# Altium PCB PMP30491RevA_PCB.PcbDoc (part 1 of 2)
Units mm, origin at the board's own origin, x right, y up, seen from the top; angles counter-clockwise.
Board outline 40.64 x 55.88 mm, 4 copper layers (Top Layer, Layer 2, Layer 3, Bottom Layer), stack 2.028 mm thick; 56 components, 28 nets, 145 pads, 91 vias.
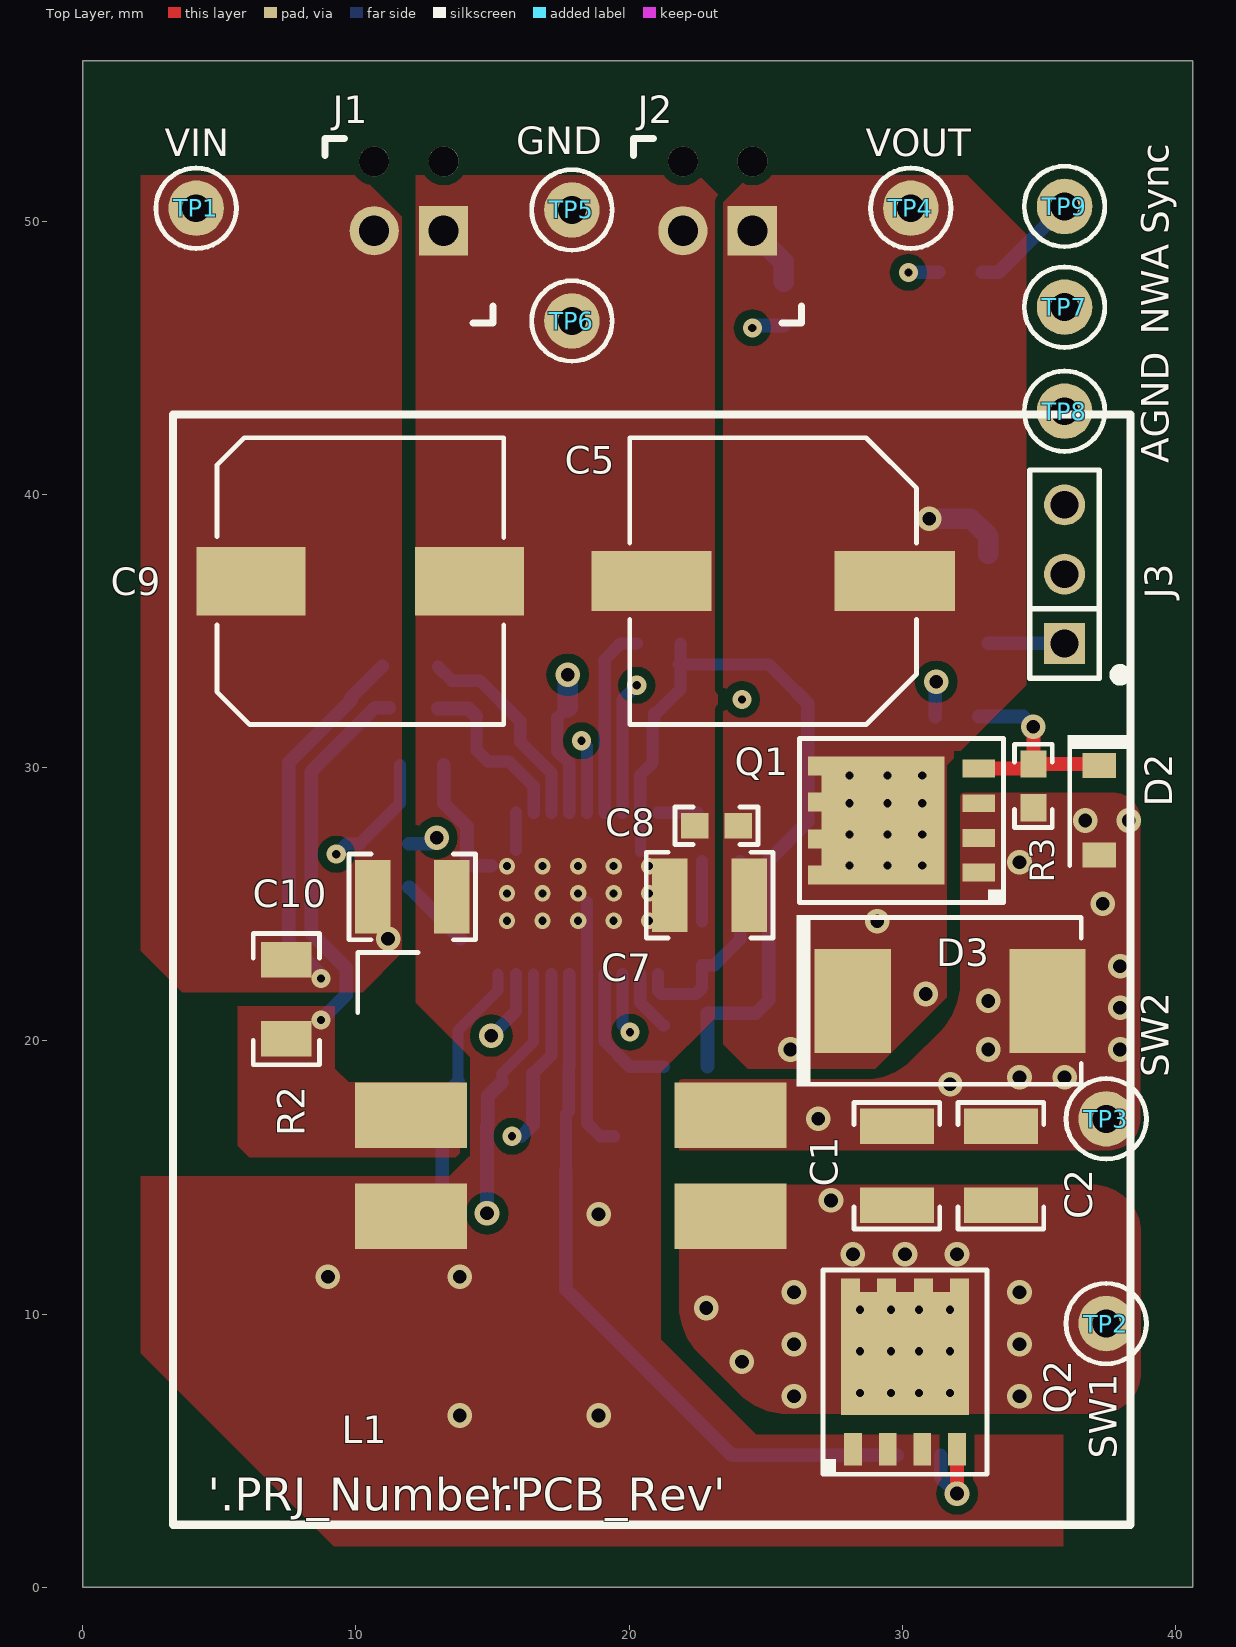
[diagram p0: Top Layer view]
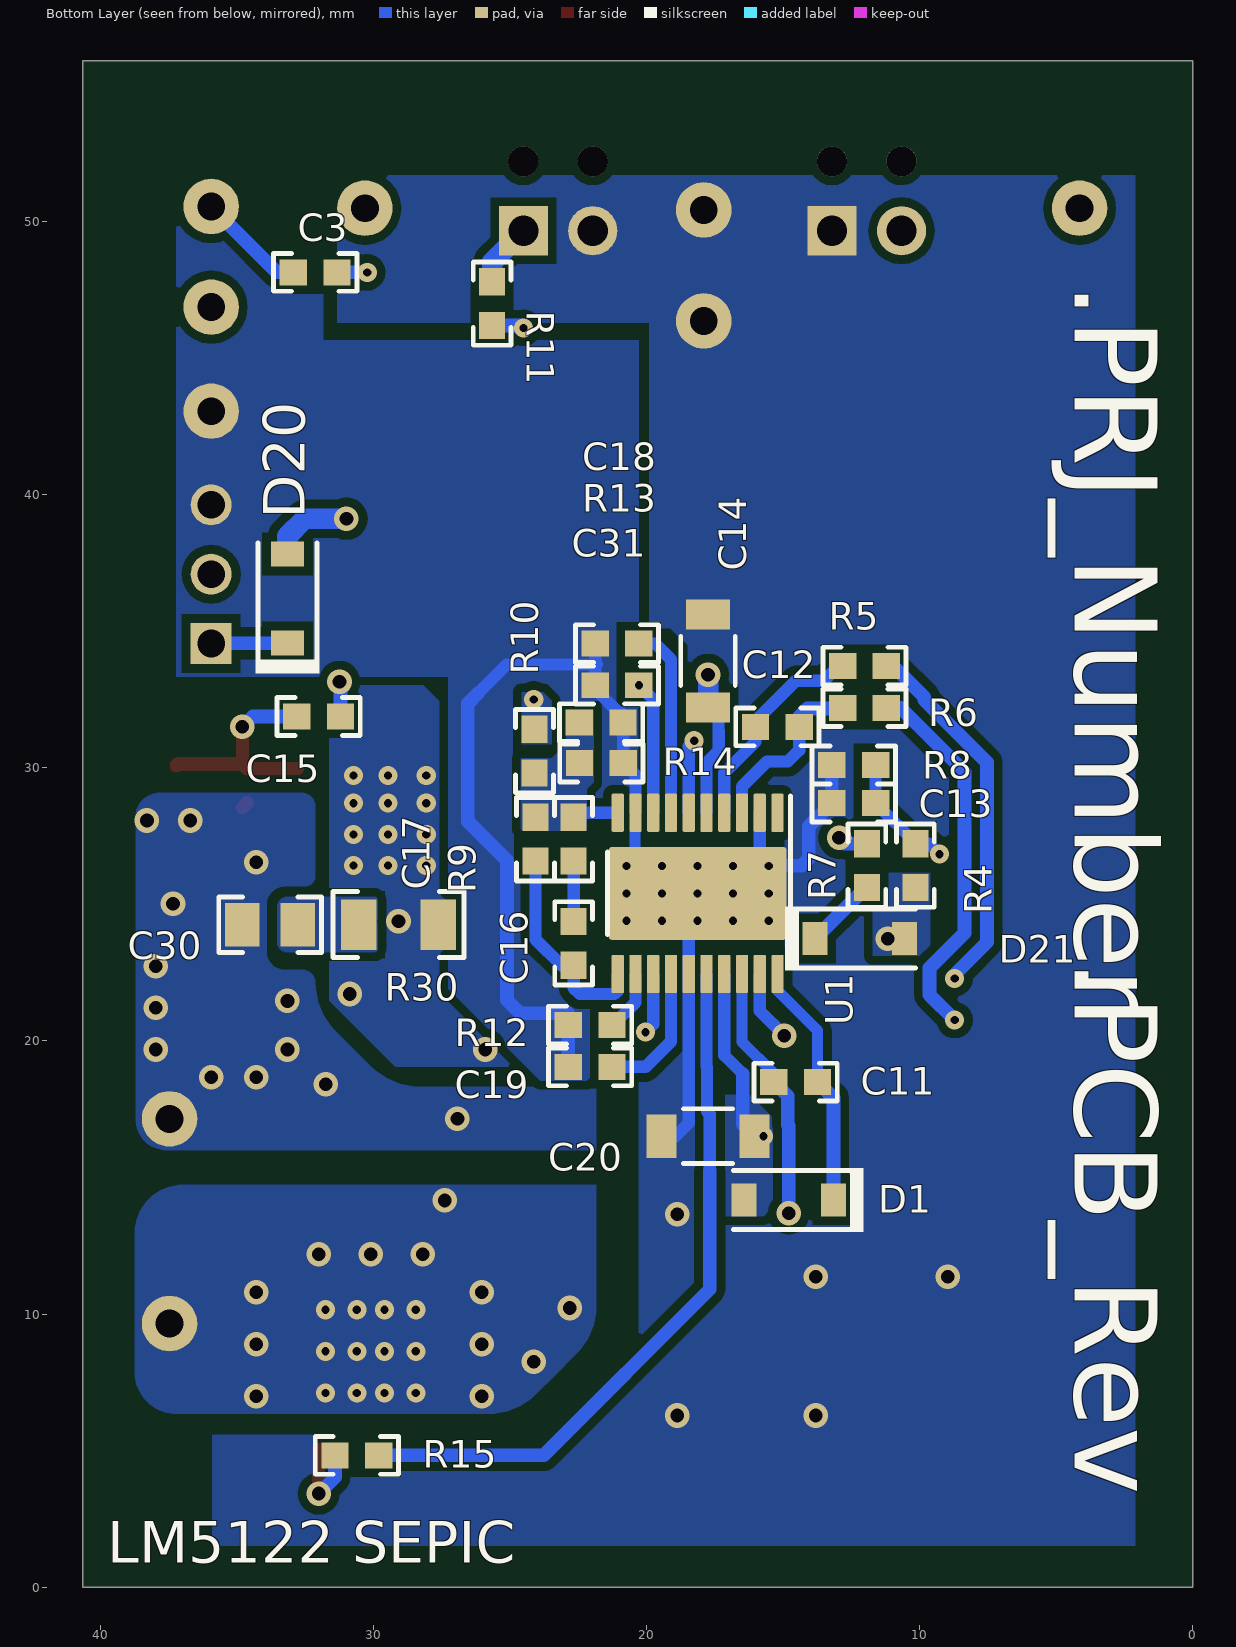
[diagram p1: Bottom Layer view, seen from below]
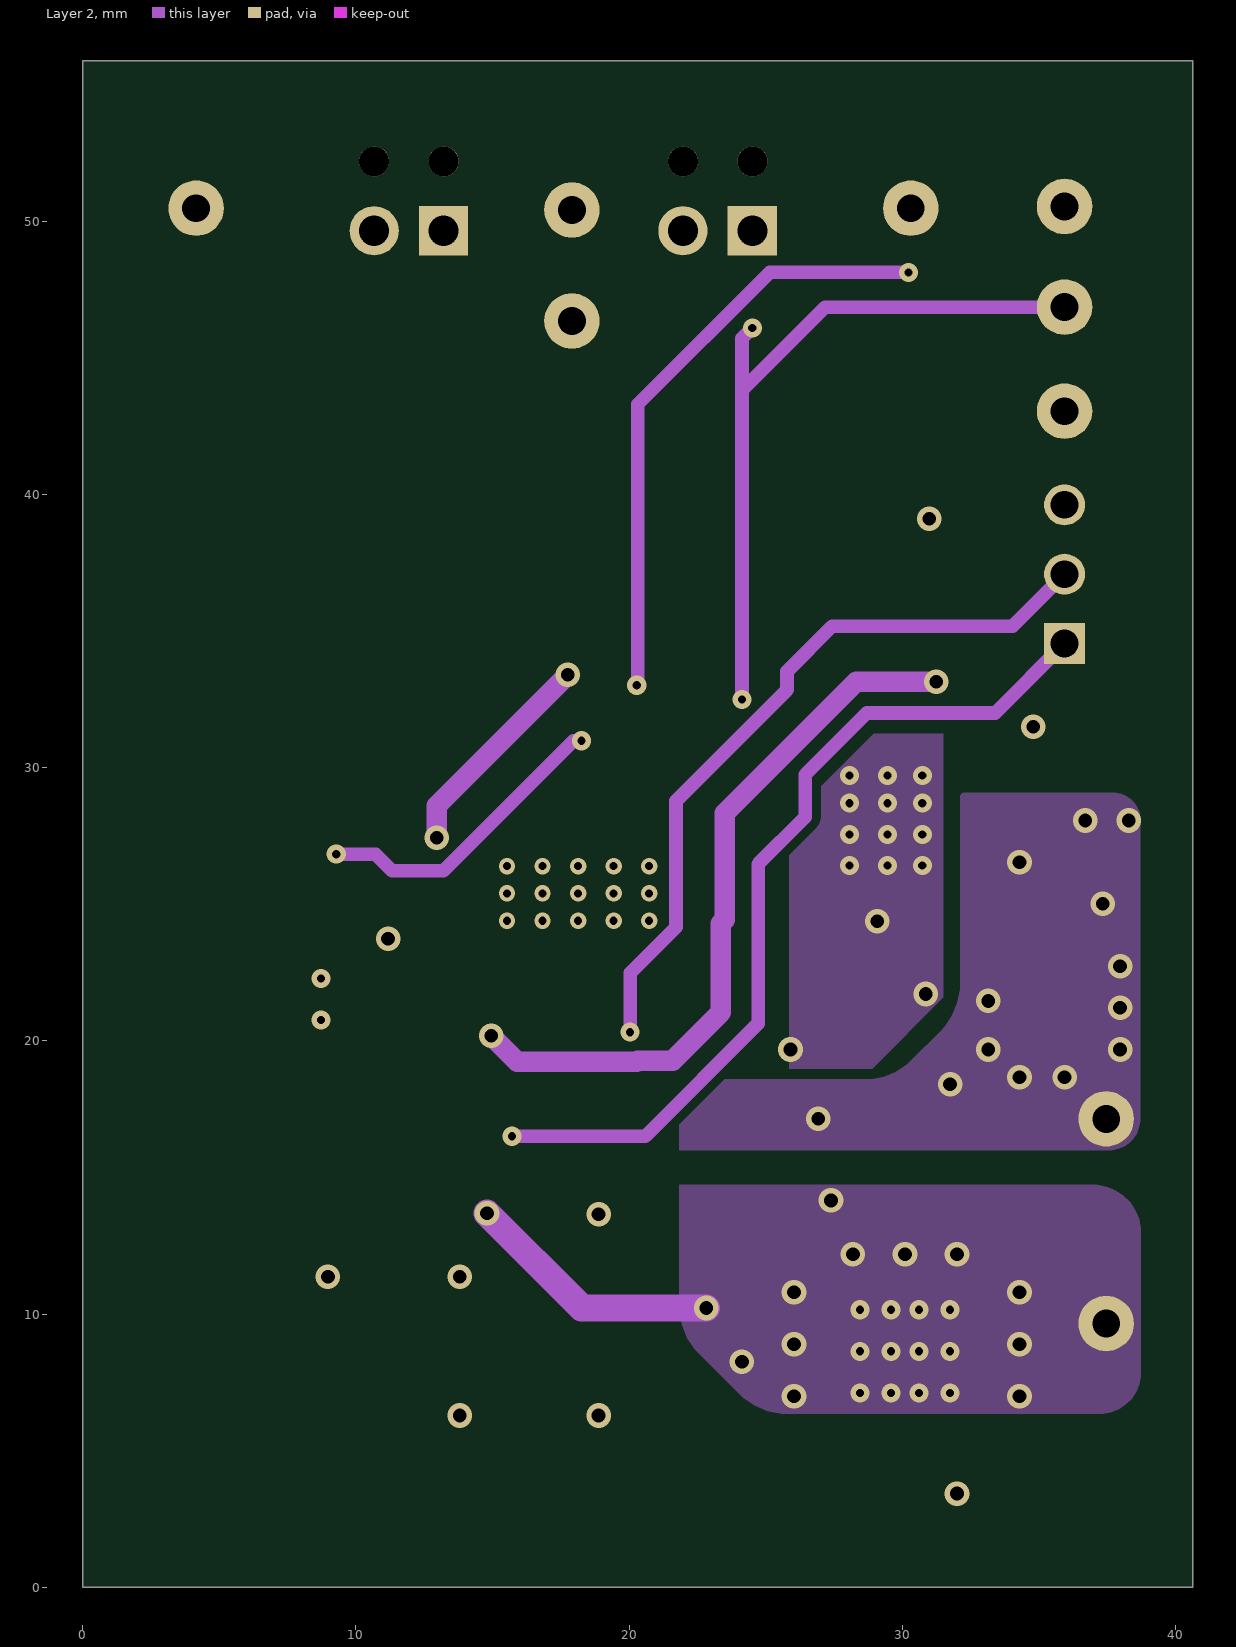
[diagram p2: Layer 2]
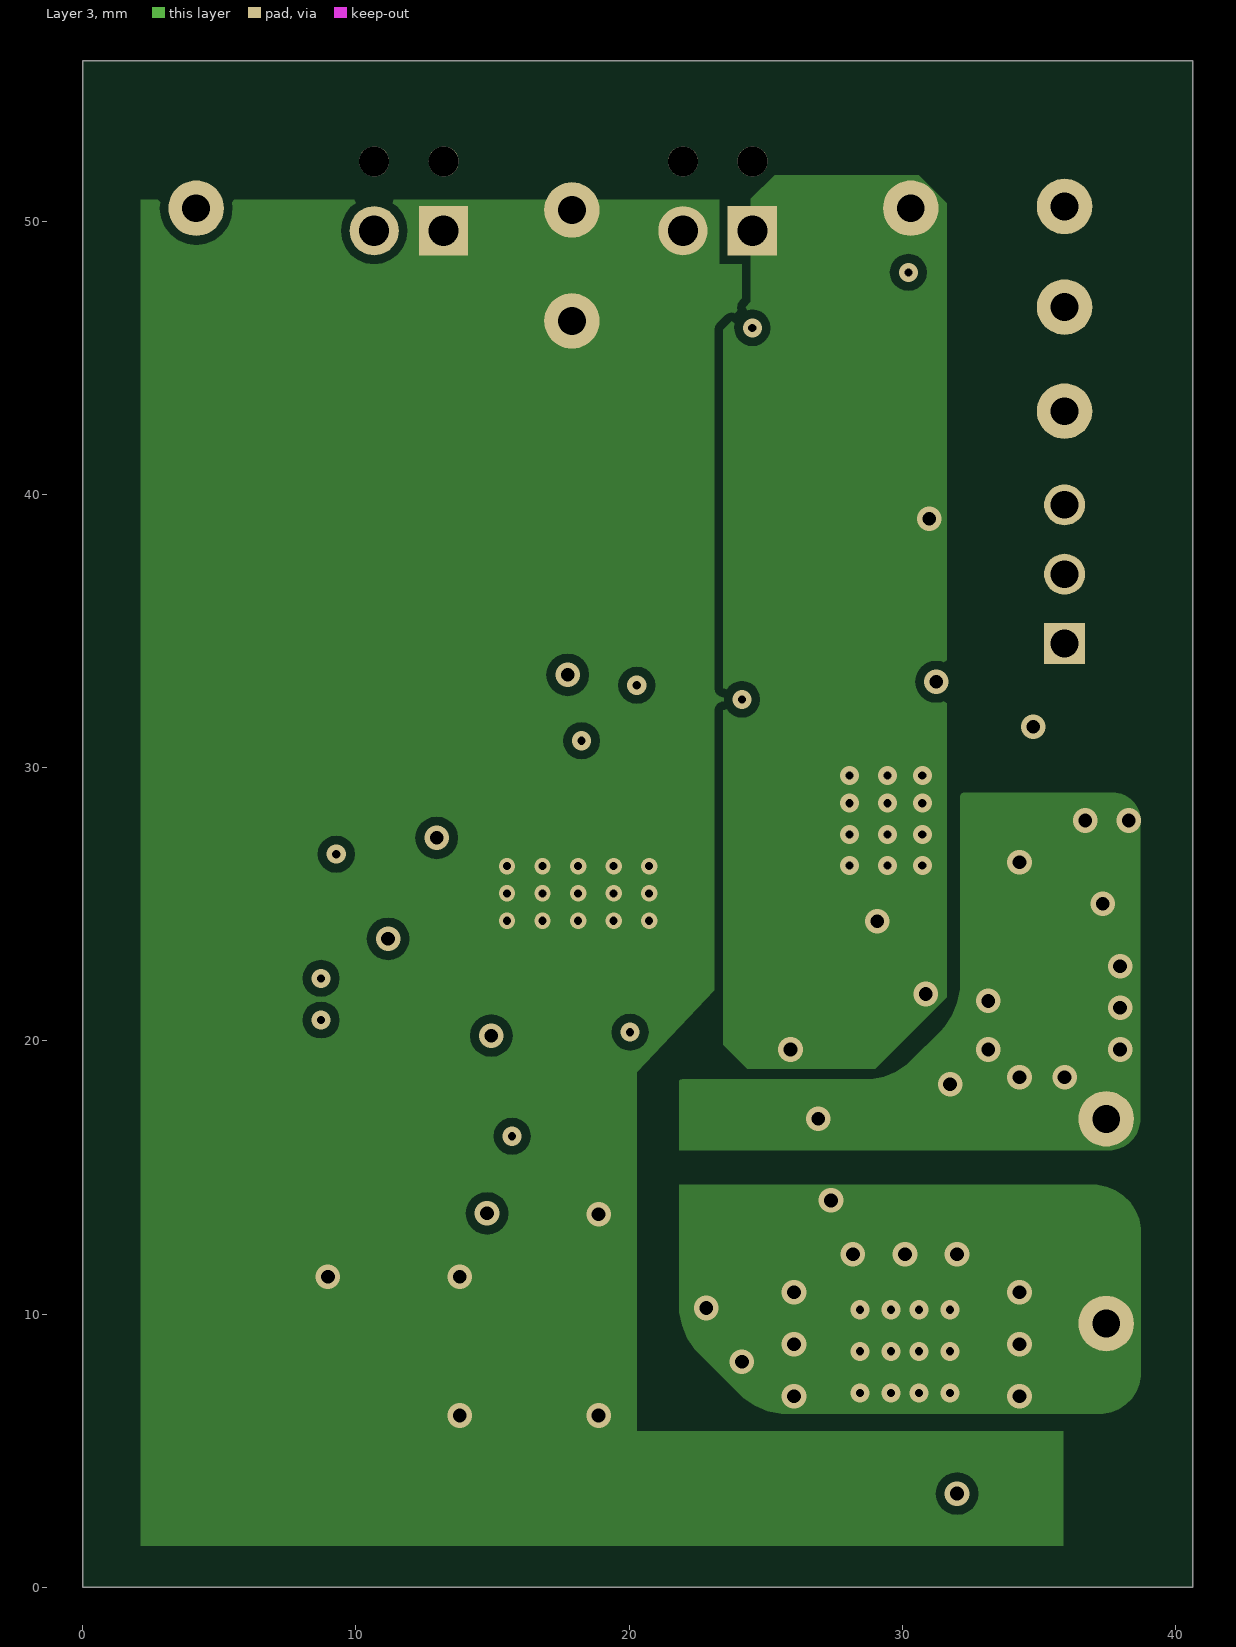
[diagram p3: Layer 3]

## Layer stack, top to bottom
Top Solder: solder mask 0.0102, Solder Resist, Dk 3.5
Top Layer: signal copper 0.0356
Dielectric1: core 1.5037, FR-4, Dk 4.8
Layer 2: signal copper 0.036
Dielectric 3: prepreg 0.127, Dk 4.2
Layer 3: signal copper 0.036
Dielectric 2: core 0.254, Dk 4.2
Bottom Layer: signal copper 0.0356
Bottom Solder: solder mask 0.0102, Solder Resist, Dk 3.5

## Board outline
0,0 40.64,0 40.64,55.88 0,55.88

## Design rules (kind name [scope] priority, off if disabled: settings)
AcuteAngle [All] p1: minimum=4.50000000000000E+0001 checktracksonly=FALSE
AssemblyTestPointUsage [All] p1: valid=2
BoardOutlineClearance BoardOutlineClearance_MountingHoles [OnCopper and InComponentClass('Mounting Holes')] p1: gap=1.016
BoardOutlineClearance BoardOutlineClearance_Poly [OnCopper and InPoly] p2: gap=0.5
BoardOutlineClearance [OnCopper and Not InComponentClass('Logo') and not InComponentClass('FiducialMark') and not InRegion(1000,500,4000,800)] p3: gap=1.5
Clearance Clearance_Keepouts [((IsTrack Or IsArc) And Not InPoly) And IsFree and IsKeepOut vs ((IsTrack Or IsArc) And Not InPoly) And IsFree and IsKeepOut] p1: gap=0
Clearance Clearance_U1_1 [TouchesRoom('Room_U1')] p2: gap=0.32 except(0.2: Arc-Track Arc-SMDPad Track-Track Track-SMDPad Track-Via SMDPad-SMDPad)
Clearance Clearance_U1 [InComponent('U1')] p3: gap=0.32 except(0.2: Arc-Track Arc-SMDPad Track-Track Track-SMDPad SMDPad-SMDPad)
Clearance Clearance_Poly [InPolygon] p4: gap=0.32
Clearance Clearance_Q [InComponent('Q1') or InComponent('Q2')] p5: gap=0.32 except(0.2: Arc-Track Arc-SMDPad Track-Track Track-SMDPad SMDPad-SMDPad; 0.3: Arc-Fill Track-Fill SMDPad-Fill)
Clearance [All] p6: gap=0.32
ComponentClearance ComponentClearance_MountingHoles_FiducialMarks [InComponentClass('Mounting Holes') vs InComponentClass('FiducialMark')] p1: gap=1.27 collisioncheckmode=3 verticalgap=0.254 showdistances=FALSE
ComponentClearance ComponentClearance_Shunt [InComponentClass('Header') vs InComponentClass('Shunt')] p2: gap=0 collisioncheckmode=3 verticalgap=0 showdistances=FALSE
ComponentClearance ComponentClearance_Logo [InComponentClass('Logo')] p3: gap=1.27 collisioncheckmode=3 verticalgap=0.254 showdistances=FALSE
ComponentClearance ComponentClearance_ScrewToNut [(HasFootprint('NY PMS 440 0025 PH')) vs (HasFootprint('Keystone_1902C'))] p4: gap=0.127 collisioncheckmode=3 verticalgap=0.254 showdistances=FALSE
ComponentClearance ComponentClearance_MountingHoles [InComponentClass('Mounting Holes')] p5: gap=6.35 collisioncheckmode=3 verticalgap=2540 showdistances=FALSE
ComponentClearance ComponentClearance_SmallPassives [HasFootprint('0201*') or HasFootprint('0402*') or HasFootprint('0508') or HasFootprint('0603*') or HasFootprint('0612') or HasFootprint('0805*') or HasFootprint('0815*') or HasFootprint('0830*') or HasFootprint('1206*') or HasFootprint('1210*') or HasFootprint('1808*') or HasFootprint('1812*') or HasFootprint('1825*') or HasFootprint('2010*') or HasFootprint('2220*') or HasFootprint('2225*') or HasFootprint('2512*') or HasFootprint('2728*') or HasFootprint('3518*') or HasFootprint('SOD-123') vs HasFootprint('0201*') or HasFootprint('0402*') or HasFootprint('0508') or HasFootprint('0603*') or HasFootprint('0612') or HasFootprint('0805*') or HasFootprint('0815*') or HasFootprint('0830*') or HasFootprint('1206*') or HasFootprint('1210*') or HasFootprint('1808*') or HasFootprint('1812*') or HasFootprint('1825*') or HasFootprint('2010*') or HasFootprint('2220*') or HasFootprint('2225*') or HasFootprint('2512*') or HasFootprint('2728*') or HasFootprint('3518*') or HasFootprint('SOD-123')] p6: gap=0.38 collisioncheckmode=3 verticalgap=0.254 showdistances=FALSE
ComponentClearance ComponentClearance_THtoSMT [IsThruComponent vs IsSMTComponent] p7: gap=1.016 collisioncheckmode=3 verticalgap=0.762 showdistances=FALSE
ComponentClearance ComponentClearance_THtoTH [IsThruComponent vs IsThruComponent] p8: gap=0.7 collisioncheckmode=3 verticalgap=0.762 showdistances=FALSE
ComponentClearance [All] p9: gap=0.762 collisioncheckmode=3 verticalgap=0.254 showdistances=FALSE
DiffPairsRouting [All] p1: maxlimit=2.54 minlimit=0.254 mostfreqgap=0.254 toplayer_minwidth=0.381 toplayer_maxwidth=0.381 toplayer_prefwidth=0.381 midlayer1_minwidth=0.381 midlayer1_maxwidth=0.381 midlayer1_prefwidth=0.381 midlayer2_minwidth=0.381 midlayer2_maxwidth=0.381 midlayer2_prefwidth=0.381 bottomlayer_minwidth=0.381 bottomlayer_maxwidth=0.381 bottomlayer_prefwidth=0.381 maxuncoupledlength=25.4
FabricationTestPointUsage TestPointUsage [All] p1: valid=2 allowmultiple=FALSE
FabricationTestpoint Testpoint [All] p1: side=3 testpointundercomponent=TRUE minsize=1.016 maxsize=2.54 preferedsize=1.524 minholesize=0 maxholesize=1.016 preferedholesize=0.813 testpointgrid=0.025 allowsidetop=TRUE allowsidebottom=TRUE usegrid=TRUE gridtolerance=0
FanoutControl Fanout_LCC [IsLCC] p1: bgadir=Out bgaviamode=Centered fanoutstyle=Auto fanoutdirection=Alternating viagrid=0.025 // Fanout_LCC (Default Rule)
FanoutControl Fanout_BGA [IsBGA] p2: bgadir=Out bgaviamode=Centered fanoutstyle=Auto fanoutdirection=Alternating viagrid=0.025 // Fanout_BGA (Default Rule)
FanoutControl Fanout_Default [All] p4: bgadir=Out bgaviamode=Centered fanoutstyle=Auto fanoutdirection=Alternating viagrid=0.025 // Fanout_Default (Default Rule)
FanoutControl Fanout_Small [(CompPinCount < 5)] p5: bgadir=Out bgaviamode=Centered fanoutstyle=Auto fanoutdirection=OutThenIn viagrid=0.025 // Fanout_Small (Default Rule)
HoleSize [All] p1: absolutevalues=TRUE maxlimit=6.375 minlimit=0.3 maxpercent=80.000 minpercent=20.000
MinimumAnnularRing MinimumAnnularRing_ThermalPadVias [IsVia and InAnyComponent] p1: minimumring=0.15
MinimumAnnularRing [All] p2: minimumring=0.2
MinimumSolderMaskSliver MinimumSolderMaskSliver_Logo [InComponentClass('Logo') vs InComponentClass('Logo')] p1: minsoldermaskwidth=0.018
MinimumSolderMaskSliver [All] p2: minsoldermaskwidth=0.1
PlaneConnect [All] p1: planeconnectstyle=Relief reliefexpansion=0.254 reliefentries=4 reliefconductorwidth=0.254 reliefairgap=0.254
PolygonConnect [All] p1: connectstyle=Direct reliefconductorwidth=0.254 reliefentries=4 polygonreliefangle="90 Angle" airgapwidth=0.254
RoomDefinition Room_U1 [InComponentClass('Components Class 1')] p1: confinementstyle=ConfineIn formatcopy=TRUE lockcomponents=FALSE outline 14.195,30.099 21.942,30.099 21.942,21.082 14.195,21.082
RoutingVias ThermalPadVias [IsVia and InAnyComponent] p1: holewidth=0.3 width=0.7 viastyle="Through Hole" minholewidth=0.3 minwidth=0.6 maxholewidth=0.5 maxwidth=1
RoutingVias [All] p2: holewidth=0.5 width=0.9 viastyle="Through Hole" minholewidth=0.3 minwidth=0.6 maxholewidth=1 maxwidth=1.8
SilkToBoardRegionClearance [Not ((IsComment or IsDesignator) And (Hide <> 'False')) and not InRegion(1000,500,4000,800)] p1:
SilkToSilkClearance SilkToSilkClearance_Pb-FreeLogo [(HasFootprint('Pb-Free_Overlay_Medium') OR HasFootprint('Pb-Free_Overlay_Small')) vs (HasFootprint('Pb-Free_Overlay_Medium') OR HasFootprint('Pb-Free_Overlay_Small'))] p1: silktosilkclearance=0
SilkToSilkClearance [All] p2: silktosilkclearance=0.102
SilkToSolderMaskClearance SilkToComponentPadClearance [IsPad and InAnycomponent] p1: minsilkscreentomaskgap=0.127 clearancetoexposedcopper=TRUE
SilkToSolderMaskClearance "Silk to Solder Mask Opening" [All] p2: minsilkscreentomaskgap=0.102 clearancetoexposedcopper=FALSE
SolderMaskExpansion [All] p1: expansion=0.05
Width [All] p1: maxlimit=2.54 minlimit=0.152 preferedwidth=0.254 checkconnectedcopper=TRUE
15 further rules are at their usual default settings.

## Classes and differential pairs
component class Header: J3

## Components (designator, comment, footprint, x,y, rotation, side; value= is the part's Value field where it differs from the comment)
C1 "GRM32ER71J106KA12L" 1210_270 29.804,15.43 r270 top
C2 "GRM32ER71J106KA12L" 1210_270 33.614,15.43 r270 top
C3 "GRM1885C1H101JA01D" 0603 32.131,48.133 r0 bottom
C5 "16SVPE470M" CAPSMT_62_JC0 25.273,36.83 r180 top
C7 "GRM32ER71E226KE15L" 1210_270 22.946,25.336 r180 top
C8 "GRM188R71E105KA12D" 0603 23.2,27.876 r180 top
C9 "EEHZC1J680P" SM_RADIAL_10BMM 10.16,36.83 r0 top
C10 "GRM32ER71J106KA12L" 1210_270 12.065,25.273 r0 top
C11 "GRM188R71E474KA12D" 0603 14.542,18.493 r0 bottom
C12 "GRM188R71H102KA01D" 0603 15.211,31.496 r0 bottom
C13 "GRM188R71H102KA01D" 0603 12.417,28.702 r0 bottom
C14 "GRM31CR72A225KA73L" 1206_190 17.751,33.909 r90 bottom
C15 "C1608X7R1C105K080AC" 0603 32.004,31.877 r180 bottom
C16 "GRM188R71E333KA01D" 0603 22.67,23.573 r90 bottom
C17 "GRM1885C1H101JA01D" 0603 24.067,27.383 r90 bottom
C18 "C1608X7R1H104K080AA" 0603 21.082,34.544 r0 bottom
C19 "GRM188R71E474KA12D" 0603 22.069,19.05 r180 bottom
C20 "GRM31CR71E106KA12L" 1206_180 17.751,16.51 r0 bottom
C30 "08051C471KAT2A" 0805_HV 33.782,24.257 r0 bottom
C31 "GRM1885C1H470JA01D" 0603 21.666,31.648 r180 bottom
D1 "MBR0580-TP" SOD-123 14.796,14.175 r0 bottom
D2 "MBR0580-TP" SOD-123 37.211,28.448 r270 top
D3 "B380-13-F" SMC 31.75,21.463 r0 top
D20 "MBR0580-TP" SOD-123 33.147,36.195 r90 bottom
D21 "MBR0580-TP" SOD-123 12.192,23.749 r180 bottom
J1 "1725656" CONN_1725656 11.938,49.657 r180 top
J2 "1725656" CONN_1725656 23.241,49.657 r180 top
J3 "PEC03SAAN" CONN_PEC03SAAN 35.941,37.084 r90 top
L1 "JA4590-AL" JA4590-AL 17.866,15.43 r0 top
Q1 "BSC117N08NS5ATMA1" PG-TDSON-8 29.972,28.067 r180 top
Q2 "BSC117N08NS5ATMA1" PG-TDSON-8 30.099,7.874 r90 top
R2 "WSLP1206R0150FEA" 1206 7.452,21.526 r270 top
R3 "CRCW06031K00FKEA" 0603 34.798,29.337 r90 top
R4 "CRCW0603100KFKEA" 0603 10.16,26.416 r270 bottom
R5 "ERJ-3GEY0R00V" 0603 12.024,33.718 r180 bottom
R6 "ERJ-3GEY0R00V" 0603 12.024,32.194 r180 bottom
R7 "CRCW06033R30JNEA" 0603 11.938,26.416 r90 bottom
R8 "CRCW060324K9FKEA" 0603 12.417,30.099 r180 bottom
R9 "CRCW060320K0FKEA" 0603 22.67,27.383 r270 bottom
R10 "CRCW060349K9FKEA" 0603 24.101,30.607 r90 bottom
R11 "CRCW060349R9FKEA" 0603 25.654,46.99 r90 bottom
R12 "CRCW060340K2FKEA" 0603 22.069,20.574 r180 bottom
R13 "CRCW060360K4FKEA" 0603 21.082,33.02 r180 bottom
R14 "CRCW06035K49FKEA" 0603 21.654,30.177 r0 bottom
R15 "CRCW06034R64FKEA" 0603 30.607,4.826 r0 bottom
R30 "PHP01206E10R0BST5" 1206 29.083,24.257 r180 bottom
TP1 "5000" Keystone5000 4.15,50.482 r0 top
TP2 "5002" Keystone5002 37.465,9.652 r90 top
TP3 "5002" Keystone5002 37.465,17.145 r90 top
TP4 "5000" Keystone5000 30.312,50.482 r0 top
TP5 "5001" Keystone5001 17.907,50.419 r0 top
TP6 "5001" Keystone5001 17.907,46.355 r0 top
TP7 "5003" Keystone5003 35.941,46.863 r180 top
TP8 "5001" Keystone5001 35.941,43.053 r90 top
TP9 "5002" Keystone5002 35.941,50.546 r0 top
U1 "LM5122MH/NOPB" PWP0020A_N 18.132,25.4 r270 bottom

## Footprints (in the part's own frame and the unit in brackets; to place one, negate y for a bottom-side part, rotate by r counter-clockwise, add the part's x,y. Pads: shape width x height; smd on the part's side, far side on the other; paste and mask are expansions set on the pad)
0603 [mm] "0603 from SM-752 data"
  rect 1x0.95 smd: 1(-0.8,0) 2(0.8,0)
  silkscreen extent -1.52,-0.69 1.52,0.69, body extent -0.87,-0.47 0.87,0.47, height 1
0805_HV [mil] "0805 with 30mil clearance between pads"
  rect 50x63 smd: 1(-40,0) 2(40,0)
  silkscreen extent -74,-40 74,40, body extent -43,-29 43,29, height 57
1206 [mm] "1206 from SM-752 data"
  rect 1.3x1.85 smd: 1(-1.45,0) 2(1.45,0)
  silkscreen extent -2.4,-1.21 2.4,1.21, body extent -1.7,-0.9 1.7,0.9, height 1.35
1206_180 [mm] "1206_180"
  rect 1.1x1.6 smd: 1(-1.7,0) 2(1.7,0)
  silkscreen extent -0.9,-1 0.9,1, body extent -1.75,-0.95 1.75,0.95, height 1.8
1206_190 [mm] "1206_190"
  rect 1.1x1.6 smd: 1(-1.7,0) 2(1.7,0)
  silkscreen extent -0.9,-1 0.9,1, body extent -1.75,-0.95 1.75,0.95, height 1.9
1210_270 [mm] "1210"
  rect 1.3x2.7 smd: 1(-1.45,0) 2(1.45,0)
  silkscreen extent -2.32,-1.57 2.32,1.57, body extent -1.7,-1.35 1.7,1.35, height 2.7
CAPSMT_62_JC0 [mm] "10 x 12.2mm:  Chemi-Con JC0"
  rect 4.4x2.2 smd: 1(-4.45,0) 2(4.45,0)
  silkscreen extent -5.25,-5.25 5.25,5.25, body extent -5.25,-5.25 5.25,5.25, height 12.7
CONN_1725656 [mm] "Phoenix Contact"
  rect 1.8x1.8 hole 1.1: 1(-1.27,0)
  round 1.8 hole 1.1: 2(1.27,0)
  round 1.1 hole 1.1 unplated: MH1(-1.275,-2.54) MH2(1.27,-2.54)
  silkscreen extent -3.08,-3.37 3.08,3.37, body extent -2.77,-3.1 2.77,3.1, height 8.52
CONN_PEC03SAAN [mm] "SULLINS"
  rect 1.5x1.5 hole 1.016: 1(-2.54,0)
  round 1.5 hole 1.016: 2(0,0) 3(2.54,0)
  silkscreen extent -3.89,-2.24 3.81,1.27, body extent -3.84,-1.3 3.84,1.3, height 8.38
JA4590-AL [mm] "COILCRAFT"
  rect 4.1x2.4 smd: 1(-5.85,1.85) 2(-5.85,-1.85) 3(5.85,-1.85) 4(5.85,1.85)
  silkscreen extent -7.8,5.6 -5.6,7.8, body extent -7.65,-7.65 7.65,7.65, height 14.25
Keystone5000 [mil] "For Keystone 500x miniature loop terminals"
  round 80 hole 40: 1(0,0)
  silkscreen extent -58,-58 58,58, body extent -49,-49 49,49, height 182
Keystone5001 [mil] "For Keystone 500x miniature loop terminals"
  round 80 hole 40: 1(0,0)
  silkscreen extent -58,-58 58,58, body extent -49,-49 49,49, height 182
Keystone5002 [mil] "For Keystone 500x miniature loop terminals"
  round 80 hole 40: 1(0,0)
  silkscreen extent -58,-58 58,58, body extent -49,-49 49,49, height 182
Keystone5003 [mil] "For Keystone 500x miniature loop terminals"
  round 80 hole 40: 1(0,0)
  silkscreen extent -58,-58 58,58, body extent -49,-49 49,49, height 182
PG-TDSON-8 [mm] "Infineon recommended land pattern"
  rect 1.2x0.65 smd: 1(-2.825,1.905) 2(-2.825,0.635) 3(-2.825,-0.635) 4(-2.825,-1.905)
  rect 0.5x0.7 smd: 5(3.175,-2) 6(3.175,-0.675) 7(3.175,0.675) 8(3.175,2)
  rect 4.5x4.7 smd paste-2.25: 9(0.675,0)
  silkscreen extent -3.74,-3 3.74,3, body extent -3.18,-2.89 3.18,2.9, height 1.1
PWP0020A_N [mm] "TSOP, 20-Leads, Body 6.5x4.4mm, Pitch 0.65mm, Exposed Pad, IPC Medium Density"
  rrect22% 1.4x0.45 smd: 1(-2.95,2.925) 2(-2.95,2.275) 3(-2.95,1.625) 4(-2.95,0.975) 5(-2.95,0.325) 6(-2.95,-0.325) 7(-2.95,-0.975) 8(-2.95,-1.625) 9(-2.95,-2.275) 10(-2.95,-2.925) 11(2.95,-2.925) 12(2.95,-2.275) 13(2.95,-1.625) 14(2.95,-0.975) 15(2.95,-0.325) 16(2.95,0.325) 17(2.95,0.975) 18(2.95,1.625) 19(2.95,2.275) 20(2.95,2.925)
  rrect6% 3.4x6.5 smd paste-2 mask-2: 21(0,0)
  rrect3% 3.15x4.35 on Bottom Paste: 21(0,0)
  rrect3% 3.15x4.35 on Bottom Solder: 21(0,0)
  silkscreen extent -3.55,-3.3 1.5,3.4, body extent -3.21,-3.25 3.21,3.25, height 1
SM_RADIAL_10BMM [mm] "Nichicon 10x10"
  rect 4x2.5 smd: 1(-4,0) 2(4,0)
  silkscreen extent -5.25,-5.25 5.25,5.25, body extent -5.25,-5.25 5.25,5.25, height 10.5
SMC [mil] "Molded Diode, 2-Leads, Body 6.9x5.8mm, IPC Medium Density, based on OnSemi component dimensions and land patterns"
  rect 110x150 smd: 1(-140.49,0) 2(140.49,0)
  silkscreen extent -221,-124 189,124, body extent -156,-116 156,116, height 91
SOD-123 [mm] "On Semi recommended land pattern"
  rect 0.915x1.22 smd: 1(-1.637,0) 2(1.637,0)
  silkscreen extent -2.74,-1.17 2.03,1.17, body extent -1.93,-0.9 1.93,0.9, height 1.35

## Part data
C1 C2 C10: "CAP, CERM, 10 µF, 63 V, +/- 10%, X7R, 1210"
C3 C17: "CAP, CERM, 100 pF, 50 V, +/- 5%, C0G/NP0, 0603"
C5: "CAP, Aluminum Polymer, 470 µF, 16 V, +/- 20%, 0.01 ohm, JC0 SMD"
C7: "CAP, CERM, 22 µF, 25 V, +/- 10%, X7R, 1210"
C8: "CAP, CERM, 1 µF, 25 V, +/- 10%, X7R, 0603"
C9: library part EEHZC1J560P, "CAP, Polymer Hybrid, 68 µF, 63 V, +/- 20%, 30 ohm, 10x10 SMD"
C11 C19: "CAP, CERM, 0.47uF, 25V, +/-10%, X7R, 0603"
C12 C13: "CAP, CERM, 1000pF, 50V, +/-10%, X7R, 0603"
C14: "CAP, CERM, 2.2 µF, 100 V, +/- 10%, X7R, 1206_190"
C15: "CAP, CERM, 1 µF, 16 V, +/- 10%, X7R, 0603"
C16: "CAP, CERM, 0.033 µF, 25 V, +/- 10%, X7R, 0603"
C18: "CAP, CERM, 0.1 µF, 50 V, +/- 10%, X7R, 0603"
C20: "CAP, CERM, 10 µF, 25 V, +/- 10%, X7R, 1206"
C30: "CAP, CERM, 470 pF, 100 V, +/- 10%, X7R, 0805"
C31: "CAP, CERM, 47 pF, 50 V, +/- 5%, C0G/NP0, 0603"
D1 D2 D20 D21: "Diode, Schottky, 80 V, 0.5 A, SOD-123"
D3: "Diode, Schottky, 80 V, 3 A, SMC"
J1 J2: "Terminal Block, 100mil, 2x1, 6A, 63V, TH"
J3: "Header, 100mil, 3x1, Tin, TH"
L1: "Coupled inductor, 22 µH, 7.8 A, 0.028 ohm, SMD"
Q1 Q2: "MOSFET, N-CH, 80 V, 49 A, PG-TDSON-8"
R2: "RES, 0.015, 1%, 1 W, 1206"
R3: "RES, 1.00k ohm, 1%, 0.1W, 0603"
R4: "RES, 100 k, 1%, 0.1 W, 0603"
R5 R6: "RES, 0 ohm, 5%, 0.1W, 0603"
R7: "RES, 3.3 ohm, 5%, 0.1W, 0603"
R8: "RES, 24.9 k, 1%, 0.1 W, 0603"
R9: "RES, 20.0 k, 1%, 0.1 W, 0603"
R10: "RES, 49.9k ohm, 1%, 0.1W, 0603"
R11: "RES, 49.9, 1%, 0.1 W, 0603"
R12: "RES, 40.2 k, 1%, 0.1 W, 0603"
R13: "RES, 60.4 k, 1%, 0.1 W, 0603"
R14: "RES, 5.49 k, 1%, 0.1 W, 0603"
R15: "RES, 4.64, 1%, 0.1 W, 0603"
R30: "RES, 10.0, 0.1%, 1 W, 1206"
TP1 TP4: "Test Point, Miniature, Red, TH"
TP2 TP3 TP9: "Test Point, Miniature, White, TH"
TP5 TP6 TP8: "Test Point, Miniature, Black, TH"
TP7: "Test Point, Miniature, Orange, TH"
U1: library part LM5122MHX/NOPB, "Wide Input Synchronous Boost Controller with Multiple Phase Capability, PWP0020A (TSSOP-20)"

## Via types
v1: diameter 0.9, hole 0.5, Top Layer to Bottom Layer, 21 vias
v2: diameter 0.7, hole 0.3, Top Layer to Bottom Layer, 19 vias
v3: diameter 0.9, hole 0.5, Top Layer to Bottom Layer, tented top, 19 vias
v4: diameter 0.7, hole 0.3, Top Layer to Bottom Layer, tented top, 9 vias
v5: diameter 0.6, hole 0.3, Top Layer to Bottom Layer, 6 vias
v6: diameter 0.6, hole 0.3, Top Layer to Bottom Layer, tented both sides, 6 vias
v7: diameter 0.7, hole 0.3, Top Layer to Bottom Layer, tented bottom, 5 vias
v8: diameter 0.6, hole 0.3, Top Layer to Bottom Layer, tented top, 3 vias
v9: diameter 0.9, hole 0.5, Top Layer to Bottom Layer, tented bottom, 2 vias
v10: diameter 0.7, hole 0.3, Top Layer to Bottom Layer, tented both sides, 1 vias

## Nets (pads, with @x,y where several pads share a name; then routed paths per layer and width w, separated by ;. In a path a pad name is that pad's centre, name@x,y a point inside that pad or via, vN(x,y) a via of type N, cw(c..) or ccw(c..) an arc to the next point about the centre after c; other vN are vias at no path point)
12V: C5.1 C7.1 C8.1 D3.1 D20.2 J2.1 Q1.5 Q1.6 Q1.7 Q1.8 Q1.9 R11.2 R30.2 TP4.1 | length 5.4
  Bottom Layer w0.75: J2.1@24.511,49.657 25.654,48.514 R11.2@25.654,47.79 ; v3(30.988,39.116) 32.512,39.116 33.147,38.481 D20.2@33.147,37.832
  other v2: 30.734,26.416 30.734,27.559 28.067,28.702 29.464,28.702 30.734,28.702 29.464,29.718 30.734,29.718
  other v3: 25.908,19.685 30.861,21.717 29.083,24.384
  other v4: 28.067,29.718
  other v7: 28.067,26.416 29.464,26.416 28.067,27.559 29.464,27.559
GND: C5.2 C7.2 C8.2 C9.2 C10.2 C13.2 C14.2 C18.2 C19.1 C20.2 C31.2 J1.1 J2.2 J3.3 L1.2 Q2.1 Q2.2 Q2.3 R8.1 R12.1 R13.1 R14.1 TP5.1 TP6.1 TP8.1 U1.2 U1.9 U1.15 U1.21@18.132,25.4 | length 44.9
  Bottom Layer w0.4: U1.9@20.407,28.35 U1.21@20.418,26.924
  Bottom Layer w0.45: v6(15.532,26.4) U1.21@15.532,26.461 ; U1.21@15.857,26.989 U1.2@15.857,28.35 ; U1.21@18.457,25.075 U1.15@18.457,22.45 18.457,16.996 18.943,16.51 C20.2@19.451,16.51 ; U1.9@20.407,28.35 20.407,29.729 R14.1@20.854,30.177 20.854,31.56 20.917,31.623 20.917,32 21.008,32 21.882,32.874 R13.1@21.882,33.02 21.882,33.782 ; C18.2@21.882,34.544 21.882,33.782 ; 26.162,32.737 25.117,33.782 21.882,33.782
  Bottom Layer w0.5: R8.1@13.217,30.099 C13.2@13.217,28.702 14.068,27.851 14.068,26.67 14.322,26.416 U1.21@14.957,26.416 ; C19.1@22.869,19.05 R12.1@22.869,20.574 22.869,21.012 24.635,21.012 25.112,21.489 25.112,26.603 26.543,28.034 26.543,32.356 26.162,32.737
  other v3: 13.802,6.286 18.882,6.286 8.976,11.366 13.802,11.366 18.882,13.652
  other v5: 16.832,24.4 16.832,25.4 18.132,25.4 16.832,26.4 18.132,26.4 19.432,26.4
  other v6: 15.532,24.4 20.732,24.4 15.532,25.4 20.732,25.4 20.732,26.4
  other v8: 18.132,24.4 19.432,24.4 19.432,25.4
NetC1_1: C1.1 C2.1 C30.2 D2.2 D3.2 L1.4 Q1.1 Q1.2 Q1.3 R3.1 TP3.1 | length 0.2
  Top Layer w0.508: R3.1@34.633,28.702 R3.1@34.798,28.537
  other v1: 26.924,17.145 31.75,18.415 34.29,18.669 35.941,18.669 33.147,19.685 37.973,19.685 33.147,21.463 37.973,22.733 36.703,28.067 38.291,28.067
  other v3: 37.973,21.209 37.338,25.019 34.29,26.543
NetC1_2: C1.2 C2.2 C11.2 L1.3 Q2.5 Q2.6 Q2.7 Q2.8 Q2.9 TP2.1 U1.18 | length 19.1
  Layer 2 w1: v3(14.799,13.685) 18.261,10.223 v3(22.819,10.223)
  Bottom Layer w0.4: C11.2@15.342,18.493 15.342,18.8 16.507,19.965 U1.18@16.507,22.45
  Bottom Layer w0.5: v3@14.703,13.589 v3(14.799,13.685) 14.799,16.891 14.83,16.922 14.83,17.98 C11.2@15.342,18.493
  other v1: 26.035,6.985 34.29,6.985 26.035,8.89 34.29,8.89 26.035,10.795 34.29,10.795 28.194,12.192 30.099,12.192 32.004,12.192
  other v2: 28.448,7.112 29.591,7.112 30.607,7.112 31.75,7.112 28.448,8.636 29.591,8.636 30.607,8.636 31.75,8.636 28.448,10.16 29.591,10.16 30.607,10.16 31.75,10.16
  other v3: 24.13,8.255 27.391,14.16
NetC3_1: C3.1 R13.2 U1.8 | length 28.2
  Layer 2 w0.5: v4@20.32,33.02 20.32,43.307 25.146,48.133 v4(30.226,48.133)
  Bottom Layer w0.45: U1.8@19.757,28.35 19.757,32.495 v4(20.282,33.02)
  Bottom Layer w0.5: v4(30.226,48.133) C3.1@31.331,48.133
NetC3_2: C3.2 TP9.1 | length 4
  Bottom Layer w0.5: C3.2@32.931,48.133 33.528,48.133 TP9.1@35.941,50.546
NetC9_1: C9.1 C10.1 D21.2 J1.2 R2.1 R4.2 R5.2 TP1.1 | length 13.3
  Bottom Layer w0.5: v4(8.722,22.288) 8.722,22.429 7.54,23.611 7.54,30.192 9.83,32.482 9.83,32.582 R5.2@10.966,33.718
  other v3: 11.176,23.736
NetC11_1: C11.1 D1.1 U1.20 | length 9.1
  Bottom Layer w0.4: C11.1@13.742,18.493 13.742,20.375 15.207,21.84 U1.20@15.207,22.45
  Bottom Layer w0.5: D1.1@13.159,14.175 13.159,17.909 C11.1@13.742,18.493
NetC12_1: C12.1 R6.1 U1.3 | length 6.4
  Bottom Layer w0.45: C12.1@14.411,31.878 C12.1@14.411,31.496 14.411,30.645 14.83,30.226 15.592,30.226 16.507,29.311 U1.3@16.507,28.35
  Bottom Layer w0.5: R6.1@13.005,32.169 14.12,32.169 C12.1@14.411,31.878
NetC12_2: C12.2 R5.1 U1.4 | length 7.7
  Bottom Layer w0.45: R5.1@13.005,33.693 13.509,33.189 14.534,33.189 16.011,31.712 C12.2@16.011,31.496 16.011,30.95 17.157,29.804 U1.4@17.157,28.35
NetC13_1: C13.1 R4.1 R8.2 U1.6 | length 18.5
  Layer 2 w0.5: v4(9.28,26.835) 10.722,26.835 11.332,26.225 13.199,26.225 17.962,30.988 v7(18.259,30.988)
  Bottom Layer w0.45: v4@9.242,26.797 v4(9.28,26.835) 9.661,27.216 R4.1@10.131,27.216 ; R4.1@10.16,27.216 R4.1@10.131,27.216 ; R8.2@11.617,30.099 C13.1@11.617,28.702 R4.1@10.131,27.216 ; v7(18.259,30.988) 18.457,30.79 U1.6@18.457,28.35
NetC14_1: C14.1 R7.2 U1.5 | length 14.5
  Layer 2 w0.75: v3(12.954,27.432) 12.954,28.604 v9(17.751,33.401)
  Bottom Layer w0.45: C14.1@17.751,32.209 17.37,31.828 17.37,31.371 17.364,31.365 17.364,30.613 17.807,30.17 U1.5@17.807,28.35
  Bottom Layer w0.508: R7.2@11.938,27.216 12.738,27.216 v3(12.954,27.432)
  Bottom Layer w0.75: C14.1@17.751,32.209 v9(17.751,33.401)
NetC15_1: C15.1 D2.1 Q1.4 R3.2 | length 8
  Top Layer w0.508: Q1.4@32.797,29.972 34.633,29.972 R3.2@34.798,30.137 ; v1(34.798,31.496) R3.2@34.798,30.137 ; D2.1@37.211,30.085 37.16,30.137 R3.2@34.798,30.137
  Bottom Layer w0.508: C15.1@32.804,31.877 34.417,31.877 v1(34.798,31.496)
NetC15_2: C15.2 U1.19 | length 30.5
  Layer 2 w0.75: v9(14.957,20.193) 15.91,19.24 20.279,19.24 20.314,19.275 21.59,19.275 23.355,21.04 23.355,24.295 23.495,24.435 23.495,28.33 28.312,33.147 v3(31.242,33.147)
  Bottom Layer w0.45: v9(14.957,20.193) 15.857,21.093 U1.19@15.857,22.45
  Bottom Layer w0.5: C15.2@31.204,31.877 v3@31.204,33.055
  Bottom Layer w0.75: v3@31.204,33.055 cw(c31.334,33.055) v3(31.242,33.147)
NetC16_1: C16.1 C17.1 U1.11 | length 7.9
  Bottom Layer w0.45: U1.11@21.057,22.45 21.057,21.84 21.18,21.717 22.45,21.717 22.67,21.937 C16.1@22.67,22.772 23.124,22.772 24.067,23.715 C17.1@24.067,26.582
NetC16_2: C16.2 R9.2 | length 2.2
  Bottom Layer w0.45: C16.2@22.67,24.372 R9.2@22.67,26.583
NetC17_2: C17.2 C31.1 R9.1 R10.1 R14.2 U1.10 | length 1.4
  Bottom Layer w0.45: U1.10@21.057,28.35 R9.1@22.503,28.35
NetC18_1: C18.1 U1.7 | length 7
  Bottom Layer w0.45: U1.7@19.107,28.35 19.107,33.966 19.685,34.544 C18.1@20.282,34.544
NetC19_2: C19.2 U1.14 | length 5
  Bottom Layer w0.45: U1.14@19.107,22.45 19.107,19.98 20.037,19.05 C19.2@21.269,19.05
NetC20_1: C20.1 D1.2 D20.1 J3.1 U1.17 | length 41.2
  Layer 2 w0.5: v4(15.719,16.51) 20.597,16.51 24.724,20.637 24.724,26.47 26.447,28.194 26.447,29.749 28.702,32.004 33.401,32.004 J3.1@35.941,34.544
  Bottom Layer w0.45: 16.481,18.796 17.157,19.472 U1.17@17.157,22.45
  Bottom Layer w0.5: C20.1@16.051,16.51 16.481,16.94 16.481,18.796 ; D20.1@33.147,34.558 35.927,34.558 J3.1@35.941,34.544
NetC30_1: C30.1 R30.1
NetD21_1: D21.1 R7.1 | length 2.7
  Bottom Layer w0.5: R7.1@11.938,25.616 11.963,25.616 D21.1@13.829,23.749
NetJ3_2: J3.2 U1.13 | length 29.5
  Layer 2 w0.5: v10(20.037,20.32) 20.037,22.493 20.055,22.493 21.719,24.157 21.719,28.786 25.781,32.848 25.781,33.528 27.432,35.179 34.036,35.179 J3.2@35.941,37.084
  Bottom Layer w0.45: U1.13@19.757,22.45 19.757,20.6 v10(20.037,20.32)
NetL1_1: L1.1 R2.2 R6.2 | length 13.8
  Bottom Layer w0.5: v4(8.722,20.764) 9.642,21.684 9.642,22.669 8.36,23.951 8.36,29.852 10.702,32.194 R6.2@11.224,32.194
NetQ2_4: Q2.4 R15.2 | length 3.3
  Top Layer w0.508: v1(32.004,3.429) Q2.4@32.004,5.049
  Bottom Layer w0.508: R15.2@31.407,4.826 31.407,4.026 v1(32.004,3.429)
NetR10_2: R10.2 R11.1 TP7.1 | length 28
  Layer 2 w0.5: v4(24.132,32.5) 24.132,43.817 ; v4(24.511,46.101) 24.132,45.722 24.132,43.817 ; TP7.1@35.941,46.863 27.178,46.863 24.132,43.817
  Bottom Layer w0.5: v4(24.511,46.101) 24.6,46.19 R11.1@25.654,46.19
NetR12_2: R12.2 U1.12 | length 2.2
  Bottom Layer w0.45: U1.12@20.407,22.45 20.407,21.411 21.244,20.574 R12.2@21.269,20.574
NetR15_1: R15.1 U1.16 | length 26.2
  Bottom Layer w0.45: 17.687,15.255 17.687,17.315 17.79,17.419 17.79,19.032 17.807,19.048 U1.16@17.807,22.45
  Bottom Layer w0.5: 17.687,15.255 17.687,10.91 23.771,4.826 R15.1@29.807,4.826
pads on no net: J1.MH1 J1.MH2 J2.MH1 J2.MH2 U1.1 U1.21@18.132,25.4

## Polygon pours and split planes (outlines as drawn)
GND on Top Layer "TOP_LAYER_GND_P012" (solid, remove dead copper, pour order 12): 12.192,51.689 22.547,51.689 23.241,50.995 23.241,20.932 21.168,18.859 21.168,9.08 24.659,5.588 35.899,5.588 35.899,1.397 9.292,1.397 2.118,8.572 2.118,15.049 13.421,15.049 14.183,15.811 14.183,16.827 14.183,19.407 13.365,20.225 12.192,21.398
12V on Top Layer "TOP_LAYER_12V_P010" (solid, remove dead copper, pour order 10): 31.623,21.59 29.019,18.986 24.343,18.986 23.454,19.875 23.454,23.304 23.454,46.048 23.454,50.708 24.434,51.689 32.385,51.689 34.544,49.53 34.544,33.02 31.623,30.099
NetL1_1 on Top Layer "TOP_LAYER_NETL1_1_P002" (solid, remove dead copper, pour order 2): 13.802,15.748 6.096,15.748 5.674,16.17 5.674,21.272 9.23,21.272 9.23,18.986 9.738,18.478 13.802,18.478
NetC9_1 on Top Layer "TOP_LAYER_NETC9_1_P000" (solid, remove dead copper, pour order 0): 2.118,51.689 10.16,51.689 11.684,50.165 11.684,23.218 10.246,21.78 7.706,21.78 3.642,21.78 2.118,23.304
NetC1_1 on Top Layer "TOP_LAYER_NETC1_1_P052" (solid, remove dead copper, pour order 52): 21.844,16.002 37.566,16.002 ccw(c37.566,17.145) 38.71,17.145 38.71,28.092 ccw(c37.719,28.092) 37.719,29.083 32.258,29.083 ccw(c32.258,28.956) 32.131,28.956 32.131,22.134 cw(c29.591,22.134) 31.387,20.338 30.353,19.304 cw(c28.623,21.034) 28.623,18.587 28.316,18.587 21.954,18.587 ccw(c21.954,18.432) 21.844,18.542
NetC1_2 on Top Layer "TOP_LAYER_NETC1_2_P060" (solid, remove dead copper, pour order 60): 21.844,14.732 36.957,14.732 cw(c36.957,12.954) 38.735,12.954 38.735,7.874 cw(c37.211,7.874) 37.211,6.35 25.817,6.35 cw(c25.817,8.89) 24.021,7.094 23.368,7.747 22.588,8.527 cw(c24.384,10.323) 21.844,10.323 21.844,11.049
NetC9_1 on Bottom Layer "BOTTOM_LAYER_NETC9_1_P014" (solid, remove dead copper, pour order 14): 9.623,26.162 9.623,23.114 11.725,23.114 11.725,26.162
NetC17_2 on Bottom Layer "BOTTOM_LAYER_NETC17_2_P016" (solid, remove dead copper, pour order 16): 22.195,27.686 24.542,27.686 24.609,27.753 24.609,30.353 23.466,30.353 22.946,30.873 22.946,32.123 21.942,32.123 21.942,29.464 22.196,29.21
NetR10_2 on Bottom Layer "BOTTOM_LAYER_NETR10_2_P018" (solid, remove dead copper, pour order 18): 23.466,30.861 24.575,30.861 24.575,32.766 23.789,32.766 23.466,32.443
GND on Bottom Layer "BOTTOM_LAYER_GND_P020" (solid, remove dead copper, pour order 20): 21.18,21.448 21.18,19.558 22.196,18.542 23.898,18.542 27.264,21.908 27.264,26.86 27.264,34.683 25.879,36.068 20.291,36.068 20.291,32.258 20.164,32.131 19.021,30.988 19.021,28.575 21.179,28.575 21.746,28.008 21.746,23.712
GND on Bottom Layer "BOTTOM_LAYER_GND_P022" (solid, remove dead copper, pour order 22): 37.211,33.337 37.211,49.974 31.836,49.974 31.836,45.656 20.279,45.656 20.279,33.337
NetC20_1 on Bottom Layer "BOTTOM_LAYER_NETC20_1_P024" (solid, remove dead copper, pour order 24): 17.116,13.589 15.719,13.589 15.211,14.097 15.211,17.018 16.227,18.034 17.116,18.034
GND on Bottom Layer "BOTTOM_LAYER_GND_P028" (solid, remove dead copper, pour order 28): 10.627,44.64 15.453,44.64 16.469,45.656 17.104,46.291 31.328,46.291 31.328,51.689 10.118,51.689 10.119,45.148
GND on Bottom Layer "BOTTOM_LAYER_GND_P050" (solid, remove dead copper, pour order 50): 19.898,46.545 15.326,46.545 10.182,51.689 2.118,51.689 2.118,1.524 35.9,1.524 35.9,5.588 23.898,5.588 20.284,9.201 20.284,23.2 20.284,26.126 18.579,27.831 18.501,27.909 18.501,34.48 19.136,35.115 19.898,35.115
NetC1_2 on Bottom Layer "BOTTOM_LAYER_NETC1_2_P066" (solid, remove dead copper, pour order 66): 21.844,14.732 36.957,14.732 cw(c36.957,12.954) 38.735,12.954 38.735,7.874 cw(c37.211,7.874) 37.211,6.35 25.817,6.35 cw(c25.817,8.89) 24.021,7.094 23.368,7.747 22.588,8.527 cw(c24.384,10.323) 21.844,10.323 21.844,11.049
NetC30_1 on Bottom Layer "BOTTOM_LAYER_NETC30_1_P070" (solid, remove dead copper, pour order 70): 30.226,23.241 33.147,23.241 ccw(c33.147,23.622) 33.528,23.622 33.528,24.892 ccw(c33.147,24.892) 33.147,25.273 29.961,25.273 ccw(c29.961,25.157) 29.845,25.157 29.845,23.368 ccw(c29.972,23.368) 29.972,23.241
NetC1_1 on Bottom Layer "BOTTOM_LAYER_NETC1_1_P072" (solid, remove dead copper, pour order 72): 21.844,16.002 37.566,16.002 ccw(c37.566,17.145) 38.71,17.145 38.71,28.19 ccw(c37.817,28.19) 37.817,29.083 32.652,29.083 ccw(c32.652,28.562) 32.131,28.562 32.131,26.035 ccw(c32.512,26.035) 32.512,25.654 33.237,25.654 cw(c33.237,24.982) 33.909,24.982 33.909,23.241 cw(c33.274,23.241) 33.274,22.606 32.603,22.606 ccw(c32.603,22.134) 32.131,22.134 cw(c29.631,22.134) 31.399,20.366 30.175,19.143 30.101,19.069 cw(c28.305,20.865) 28.305,18.325 21.844,18.325
12V on Bottom Layer "BOTTOM_LAYER_12V_P076" (solid, remove dead copper, pour order 76): 25.019,19.05 29.21,19.05 31.623,21.463 31.623,33.147 28.312,33.147 27.677,32.512 27.559,32.394 27.559,25.367 26.947,25.367 26.947,23.345 26.959,23.357 27.383,23.357 27.432,23.357 27.559,23.23 27.559,21.844 27.559,21.717 24.892,19.05
12V on Layer 2 "LAYER_2_12V_P040" (solid, remove dead copper, pour order 40): 25.867,18.986 28.892,18.986 31.496,21.59 31.496,31.242 28.956,31.242 25.866,28.152
NetC1_1 on Layer 2 "LAYER_2_NETC1_1_P054" (solid, remove dead copper, pour order 54): 21.844,16.002 37.566,16.002 ccw(c37.566,17.145) 38.71,17.145 38.71,28.092 ccw(c37.719,28.092) 37.719,29.083 32.258,29.083 ccw(c32.258,28.956) 32.131,28.956 32.131,22.134 cw(c29.591,22.134) 31.387,20.338 30.353,19.304 cw(c28.623,21.034) 28.623,18.587 28.316,18.587 21.954,18.587 ccw(c21.954,18.432) 21.844,18.542
NetC1_2 on Layer 2 "LAYER_2_NETC1_2_P062" (solid, remove dead copper, pour order 62): 21.844,14.732 36.957,14.732 cw(c36.957,12.954) 38.735,12.954 38.735,7.874 cw(c37.211,7.874) 37.211,6.35 25.817,6.35 cw(c25.817,8.89) 24.021,7.094 23.368,7.747 22.588,8.527 cw(c24.384,10.323) 21.844,10.323 21.844,11.049
GND on Layer 3 "LAYER_3_GND_P044" (solid, remove dead copper, pour order 44): 2.118,50.8 31.836,50.8 31.836,31.051 20.279,18.859 20.279,5.715 35.9,5.715 35.9,1.524 2.118,1.524
12V on Layer 3 "LAYER_3_12V_P042" (solid, remove dead copper, pour order 42): 31.623,21.59 29.008,18.975 24.332,18.975 23.443,19.864 23.443,23.293 23.443,46.037 24.458,47.053 24.458,50.824 25.323,51.689 30.607,51.689 31.623,50.673
NetC1_1 on Layer 3 "LAYER_3_NETC1_1_P056" (solid, remove dead copper, pour order 56): 21.844,16.002 37.566,16.002 ccw(c37.566,17.145) 38.71,17.145 38.71,28.092 ccw(c37.719,28.092) 37.719,29.083 32.258,29.083 ccw(c32.258,28.956) 32.131,28.956 32.131,22.134 cw(c29.591,22.134) 31.387,20.338 30.353,19.304 cw(c28.623,21.034) 28.623,18.587 28.316,18.587 21.954,18.587 ccw(c21.954,18.432) 21.844,18.542
NetC1_2 on Layer 3 "LAYER_3_NETC1_2_P064" (solid, remove dead copper, pour order 64): 21.844,14.732 36.957,14.732 cw(c36.957,12.954) 38.735,12.954 38.735,7.874 cw(c37.211,7.874) 37.211,6.35 25.817,6.35 cw(c25.817,8.89) 24.021,7.094 23.368,7.747 22.588,8.527 cw(c24.384,10.323) 21.844,10.323 21.844,11.049

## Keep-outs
Keep-Out Layer:
  text ".Layer_Name" at 13.386,-25.616 h1.52

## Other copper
Top Layer:
  text ".Layer_Name" at 13.386,-25.616 h1.52
Bottom Layer:
  pour cut-out: 20.152,26.86 20.152,27.749 14.945,27.749 14.945,26.86
  pour cut-out: 20.533,23.812 20.533,22.923 14.945,22.923 14.945,23.812
  text ".Layer_Name" at 13.386,-25.616 h1.52

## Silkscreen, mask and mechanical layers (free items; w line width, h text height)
Top Overlay:
  lines w0.3: 3.302,2.286 3.302,42.926 38.354,42.926 38.354,2.286 3.302,2.286
  text "GND" at 15.875,52.451 h1
  text "VIN" at 3.007,52.387 h1
  text "VOUT" at 28.661,52.387 h1
  text "Sync" at 39.751,49.53 h1 r90
  text "NWA" at 39.751,45.847 h1 r90
  text "AGND" at 39.751,41.148 h1 r90
  text "SW2" at 39.751,18.669 h1 r90
  text "SW1" at 37.846,4.699 h1 r90
  text "'.PRJ_Number'" at 4.572,2.794 h1.2
  text "'.PCB_Rev'" at 14.859,2.794 h1.2
  text ".Layer_Name" at 13.386,-25.616 h1.52
Bottom Overlay:
  text ".PRJ_Number" at 4.318,47.752 h3.05 r90
  text ".PCB_Rev" at 4.318,22.987 h3.05 r90
  text "LM5122 SEPIC" at 39.751,0.889 h1.52
  text ".Layer_Name" at 13.386,-25.616 h1.52
Top Paste:
  text ".Layer_Name" at 13.386,-25.616 h1.52
Bottom Paste:
  text ".Layer_Name" at 13.386,-25.616 h1.52
Top Solder:
  text ".Layer_Name" at 13.386,-25.616 h1.52
  text ".Layer_Name" at 13.386,-25.616 h1.52
Bottom Solder:
  text ".Layer_Name" at 13.386,-25.616 h1.52
Drill Guide:
  text ".Layer_Name" at 13.386,-25.616 h1.52
M1 Board Outline:
  the board outline again, w0.45
  text ".Layer_Name" at 13.386,-25.616 h1.52
M2 Board Dimensions:
  rectangle: -1.27,-10.795 1.905,-7.62
  rectangle: 1.905,-13.97 11.43,-10.795
  lines w0.178: -1.27,-10.795 24.13,-10.795 ; 1.905,-13.97 1.905,-7.62 ; 5.08,-13.97 5.08,-7.62 ; 11.43,-13.97 11.43,-7.62 ; 17.78,-13.97 17.78,-7.62 ; -1.27,-13.97 24.13,-13.97 24.13,-7.62 -1.27,-7.62 -1.27,-13.97
  text "'.Print_Date'" at 0.381,57.404 h1.52
  text "'.Print_Time'" at 14.605,57.404 h1.52
  text ".Layer_Name" at 13.386,-25.616 h1.52
M3 3D STEP Top:
  text ".Layer_Name" at 13.386,-25.616 h1.52
M4 3D STEP Bottom:
  text ".Layer_Name" at 13.386,-25.616 h1.52
M5 Assembly Top:
  lines w0.254: -8.687,-27.436 158.953,-27.436 ; -8.687,-22.272 159.004,-22.272 ; -8.687,-17.107 -8.687,-32.601 93.04,-32.601 159.004,-32.601 159.004,-17.107 -8.674,-17.107 -8.674,-32.601 31.344,-32.601 ; 53.924,-32.601 53.924,-17.107 ; 86.106,-22.272 86.106,-17.107 ; 107.442,-22.272 107.442,-17.107 ; 123.241,-32.766 123.241,-27.614
  text "COMPONENTS MARKED 'DNP' SHOULD NOT BE POPULATED." at 28.029,-11.9 h1.52
  text "ASSEMBLY VARIANT:" at 28.016,-14.834 h1.52
  text ".VariantName" at 54.331,-14.834 h1.52
  text "PCB VIEWED FROM TOP SIDE" at -7.074,-20.464 h1.52
  text "BOARD #:" at 55.829,-20.464 h1.52
  text ".PRJ_Number" at 69.685,-20.464 h1.52
  text "REV:" at 91.135,-20.464 h1.52
  text ".PCB_Rev" at 98.539,-20.464 h1.52
  text "SVN REV:" at 112.42,-20.464 h1.52
  text ".VersionControl_RevNumber" at 125.273,-20.464 h1.52
  text "TID #:" at 55.829,-25.629 h1.52
  text ".TID" at 69.685,-25.629 h1.52
  text "PLOT NAME =" at -7.074,-30.844 h1.52
  text ".plot_File_Name" at 13.386,-30.844 h1.52
  text "GENERATED    :" at 55.88,-30.844 h1.52
  text ".Print_Date" at 77.965,-30.844 h1.52
  text ".Print_Time" at 96.482,-30.844 h1.52
  text "TEXAS INSTRUMENTS" at 128.6,-30.844 h1.52
M6 Assembly Bottom:
  lines w0.254: -8.7,-22.284 158.991,-22.284 ; -8.649,-27.449 158.991,-27.449 ; 27.064,-32.779 27.064,-27.627 ; 42.862,-22.284 42.862,-17.12 ; 64.198,-22.284 64.198,-17.12 ; 96.38,-32.614 96.38,-17.12 ; 118.961,-32.614 158.979,-32.614 158.979,-17.12 -8.7,-17.12 -8.7,-32.614 57.264,-32.614 158.991,-32.614 158.991,-17.12
  text "COMPONENTS MARKED 'DNP' SHOULD NOT BE POPULATED." at 153.721,-11.887 h1.52
  text ".VariantName" at 127.203,-14.834 h1.52
  text "ASSEMBLY VARIANT:" at 153.594,-14.834 h1.52
  text ".VersionControl_RevNumber" at 25.032,-20.477 h1.52
  text "SVN REV:" at 37.884,-20.477 h1.52
  text ".PCB_Rev" at 51.765,-20.477 h1.52
  text "REV:" at 59.169,-20.477 h1.52
  text ".PRJ_Number" at 80.62,-20.477 h1.52
  text "BOARD #:" at 94.475,-20.477 h1.52
  text "PCB VIEWED FROM BOTTOM SIDE" at 157.378,-20.477 h1.52
  text ".TID" at 80.62,-25.641 h1.52
  text "TID #:" at 94.475,-25.641 h1.52
  text "TEXAS INSTRUMENTS" at 21.704,-30.857 h1.52
  text ".Print_Time" at 53.823,-30.857 h1.52
  text ".Print_Date" at 72.339,-30.857 h1.52
  text "GENERATED    :" at 94.424,-30.857 h1.52
  text ".plot_File_Name" at 136.919,-30.857 h1.52
  text "PLOT NAME =" at 157.378,-30.857 h1.52
M9 Title Sheet:
  drawing of 57 lines, arcs and shapes, not listed
  text "1" at 17.522,200.317 h1.78
  text "2" at 80.912,200.317 h1.78
  text "3" at 144.141,200.317 h1.78
  text "4" at 207.81,200.317 h1.78
  text "5" at 271.285,200.317 h1.78
  text "6" at 334.912,200.317 h1.78
  text "A" at -11.849,171.285 h1.78
  text "A" at 364.071,171.285 h1.78
  text "B" at -11.849,110.833 h1.78
  text "B" at 364.071,110.833 h1.78
  text "C" at -11.849,50.508 h1.78
  text "C" at 364.071,50.508 h1.78
  text "PROJECT TITLE:" at 286.855,3.238 h1.14
  text ".PRJ_Title" at 288.125,-0.148 h1.78
  text "DESIGNED FOR:" at 286.855,-4.407 h1.14
  text ".PRJ_Customer" at 288.125,-7.963 h1.78
  text "D" at -11.849,-9.69 h1.78
  text "D" at 364.071,-9.69 h1.78
  text "FILE NAME:" at 286.855,-12.027 h1.14
  text ".PCB_File_Name_No_Path" at 288.125,-15.075 h1.78
  text "Texas Instruments (TI) and/or its licensors do not warrant the accuracy or completeness of this specification" at 160.63,-19.186 h1.14
  text "ENGINEER:" at 286.855,-19.393 h1.14
  text "LAYOUT BY:" at 325.082,-19.393 h1.14
  text "or any information contained therein. TI and/or its licensors do not warrant that this design will meet" at 159.487,-22.047 h1.14
  text ".PRJ_Engineer" at 288.125,-23.33 h1.78
  text ".PCB_Layout" at 326.365,-23.33 h1.78
  text "the specifications, will be suitable for your application or fit for any particular purpose, or will operate in" at 159.487,-24.909 h1.14
  text ".Layer_Name" at 13.386,-25.616 h1.52
  text "ALTIUM DESIGNER VERSION:" at 325.082,-27.267 h1.14
  text "an implementation. TI and/or its licensors do not warrant that the design is production worthy. You should" at 159.487,-27.771 h1.14
  text "completely validate and test your design implementation to confirm the system functionality for your application." at 160.63,-30.632 h1.14
  text ".print_Scale" at 288.125,-30.653 h1.78
  text ".Application_BuildNumber" at 326.365,-30.653 h1.78
  text "1" at 17.522,-35.903 h1.78
  text "2" at 80.912,-35.903 h1.78
  text "3" at 144.141,-35.903 h1.78
  text "4" at 207.81,-35.903 h1.78
  text "5" at 271.285,-35.903 h1.78
  text "6" at 334.912,-35.903 h1.78
M10 Fab Notes:
  drawing of 173 lines, arcs and shapes, not listed
  text "DESIGN INFORMATION" at 313.132,153.695 h1.52
  text "MIN. TRACK WIDTH:" at 296.76,149.123 h1.52
  text "8" at 324.604,149.123 h1.52
  text "MIL" at 328.535,149.123 h1.52
  text "MIN. CLEARANCE:" at 296.76,145.771 h1.52
  text "0.2" at 323.08,145.771 h1.52
  text "mm" at 328.535,145.771 h1.52
  text "MIN. VIA PAD SIZE:" at 296.76,142.418 h1.52
  text "24" at 323.843,142.418 h1.52
  text "MIL" at 328.535,142.418 h1.52
  text "0.05mm (2MIL)" at 314.413,138.818 h1.52
  text "MINIMUM ANNULAR RING" at 288.397,138.71 h1.52
  text "EXTERNAL" at 332.396,138.71 h1.52
  text "PER" at 293.477,135.712 h1.52
  text "IPC-D-275 CLASS 2 LEVEL C" at 299.065,135.712 h1.52
  text "MIL, HOLES" at 336.866,132.86 h1.52
  text "+/-" at 326.898,132.842 h1.52
  text "+/-" at 348.59,132.842 h1.52
  text "REGISTRATION TOLERANCES:" at 288.397,132.715 h1.52
  text "METAL" at 318.872,132.715 h1.52
  text "5" at 333.507,132.715 h1.52
  text "3" at 354.665,132.715 h1.52
  text "MIL" at 357.618,132.715 h1.52
  text "+/-" at 348.59,129.845 h1.52
  text "HOLE SIZE TOLERANCE (UNLESS OTHERWISE SPECIFIED):" at 288.397,129.718 h1.52
  text "3" at 354.665,129.718 h1.52
  text "MIL" at 357.618,129.718 h1.52
  text "MATERIAL:" at 286.498,124.398 h1.52
  text "FR-4 High Tg" at 311.554,120.833 h1.52
  text "FR-408" at 297.192,120.615 h1.52
  text "OTHER" at 334.987,120.615 h1.52
  text "X" at 307.619,120.523 h1.52
  text "62 MIL (1.6mm) +/-10%" at 305.322,116.482 h1.52
  text "THICKNESS:" at 288.397,116.374 h1.52
  text "X" at 302.067,116.374 h1.52
  text "OTHER" at 337.959,116.374 h1.52
  text "TOLERANCE:" at 288.397,112.36 h1.52
  text "X" at 309.716,112.36 h1.52
  text "ANSI IPC-6012 TYPE 3 CLASS 2" at 314.464,112.36 h1.52
  text "OTHER +/-" at 314.464,108.398 h1.52
  text "BOW & TWIST:" at 288.397,104.41 h1.52
  text "X" at 309.716,104.41 h1.52
  text "ANSI IPC-6012 TYPE 3 CLASS 2" at 314.464,104.41 h1.52
  text "OTHER +/-" at 314.464,100.384 h1.52
  text "DRILLING:" at 286.498,96.866 h1.52
  text "REFERENCE:" at 288.397,93.895 h1.52
  text "X" at 304.862,93.895 h1.52
  text "AS SHOWN" at 309.612,93.895 h1.52
  text "X" at 327.748,93.895 h1.52
  text "NC_DRILL FILES" at 331.228,93.895 h1.52
  text "PTH MIN COPPER THICKNESS:" at 288.397,89.881 h1.52
  text "X" at 322.693,89.881 h1.52
  text "1MIL" at 326.173,89.881 h1.52
  text "OTHER" at 338.797,89.881 h1.52
  text "BOARD FINISH:" at 286.498,85.843 h1.52
  text "SILKSCREEN:" at 290.441,82.846 h1.52
  text "X" at 314.54,82.846 h1.52
  text "TOP" at 317.74,82.846 h1.52
  text "X" at 327.494,82.846 h1.52
  text "BOTTOM" at 330.72,82.846 h1.52
  text "SILKSCREEN COLOR:" at 290.441,78.604 h1.52
  text "X" at 314.513,78.604 h1.52
  text "WHITE" at 317.74,78.604 h1.52
  text "OTHER" at 330.72,78.604 h1.52
  text "X" at 317.841,74.56 h1.52
  text "GREEN" at 321.068,74.56 h1.52
  text "OTHER" at 336.765,74.56 h1.52
  text "SOLDER RESIST COLOR:" at 290.441,74.286 h1.52
  text "X" at 317.841,70.242 h1.52
  text "MATTE" at 321.068,70.242 h1.52
  text "SEMI-GLOSS" at 336.753,70.226 h1.52
  text "IMMERSION GOLD (ENIG)" at 313.448,65.454 h1.52
  text "ENEPIG" at 347.421,65.37 h1.52
  text "SURFACE FINISH:" at 286.498,65.345 h1.52
  text "X" at 308.699,65.345 h1.52
  text "IMM. TIN/SILVER OR EQUIV" at 294.869,61.357 h1.52
  text "OTHER" at 331.228,61.357 h1.52
  text "ARRAY/PANEL:" at 286.498,56.811 h1.52
  text "CUT AND TRIM PER M1 BOARD OUTLINE" at 313.448,56.702 h1.52
  text "N.C. ROUTE" at 313.448,52.848 h1.52
  text "X" at 330.694,52.848 h1.52
  text "V. SCORE" at 335.444,52.848 h1.52
  text "CERTIFICATION:" at 286.498,49.368 h1.52
  text "MATERIALS AND WORKMANSHIP FOR ALL PCBS" at 304.913,49.368 h1.52
  text "TO MEET OR EXCEED THE REQUIREMENTS OF:" at 304.913,46.879 h1.52
  text "X" at 295.426,43.412 h1.52
  text "ANSI IPC-A-600F CLASS ->" at 298.957,43.412 h1.52
  text "X" at 340.589,43.412 h1.52
  text "2" at 343.61,43.412 h1.52
  text "1" at 335.609,43.374 h1.52
  text "3" at 352.602,43.374 h1.52
  text "X" at 316.103,39.361 h1.52
  text "RoHS" at 319.582,39.361 h1.52
  text "OTHER" at 335.95,39.361 h1.52
  text "PER ORDER" at 346.035,39.361 h1.52
  text "ALL BOARDS MUST MEET OR EXCEED UL94-V0 REQUIREMENTS." at 287.198,35.154 h1.52
  text "PCB MUST BEAR THE UL94V-0 UL REGISTERED MATERIAL ID NUMBER" at 287.198,32.106 h1.52
  text "ADDITIONAL REQUIREMENTS:" at 286.498,27.702 h1.52
  text "MICROSECTION:" at 288.397,24.781 h1.52
  text "YES" at 311.403,24.781 h1.52
  text "REQUIRED" at 333.285,20.815 h1.52
  text "BARE BOARD ELEC. TEST:" at 288.397,20.743 h1.52
  text "NONE" at 321.563,20.743 h1.52
  text "X" at 330.059,20.743 h1.52
  text "PER ORDER" at 348.322,20.743 h1.52
  text ".Layer_Name" at 13.386,-25.616 h1.52
M11 Gerber Information:
  lines w0.254: -8.687,-27.436 158.953,-27.436 ; -8.687,-22.272 159.004,-22.272 ; -8.687,-17.107 -8.687,-32.601 93.04,-32.601 159.004,-32.601 159.004,-17.107 -8.674,-17.107 -8.674,-32.601 31.344,-32.601 ; 53.924,-32.601 53.924,-17.107 ; 86.106,-22.272 86.106,-17.107 ; 107.442,-22.272 107.442,-17.107 ; 123.241,-32.766 123.241,-27.614
  text "ALL ARTWORK VIEWED FROM TOP SIDE" at -7.074,-20.464 h1.52
  text "BOARD #:" at 55.829,-20.464 h1.52
  text ".PRJ_Number" at 69.685,-20.464 h1.52
  text "REV:" at 91.135,-20.464 h1.52
  text ".PCB_Rev" at 98.539,-20.464 h1.52
  text "SVN REV:" at 112.42,-20.464 h1.52
  text ".VersionControl_RevNumber" at 125.273,-20.464 h1.52
  text "LAYER NAME =" at -7.074,-25.616 h1.52
  text "TID #:" at 55.829,-25.629 h1.52
  text ".TID" at 69.685,-25.629 h1.52
  text "PLOT NAME =" at -7.074,-30.844 h1.52
  text ".plot_File_Name" at 13.386,-30.844 h1.52
  text "GENERATED    :" at 55.88,-30.844 h1.52
  text ".Print_Date" at 77.965,-30.844 h1.52
  text ".Print_Time" at 96.482,-30.844 h1.52
  text "TEXAS INSTRUMENTS" at 128.6,-30.844 h1.52
M12 Stackup:
  drawing of 191 lines, arcs and shapes, not listed
  text "Layer" at 247.405,195.072 h1.52
  text "Name" at 257.816,195.072 h1.52
  text "Material" at 281.432,195.072 h1.52
  text "Thickness" at 303.27,195.072 h1.52
  text "Constant" at 319.776,195.072 h1.52
  text "Board Layer Stack" at 334.25,195.072 h1.52
  text "1" at 247.405,192.024 h1.52
  text "Top Overlay" at 257.816,192.024 h1.52
  text "2" at 247.405,188.976 h1.52
  text "Top Solder" at 257.816,188.976 h1.52
  text "Solder Resist" at 281.432,188.976 h1.52
  text "0.40mil" at 303.27,188.976 h1.52
  text "3.5" at 319.776,188.976 h1.52
  text "3" at 247.405,185.928 h1.52
  text "Top Layer" at 257.816,185.928 h1.52
  text "Copper" at 281.432,185.928 h1.52
  text "1.40mil" at 303.27,185.928 h1.52
  text "4" at 247.405,182.88 h1.52
  text "Dielectric1" at 257.816,182.88 h1.52
  text "FR-4" at 281.432,182.88 h1.52
  text "59.20mil" at 303.27,182.88 h1.52
  text "4.8" at 319.776,182.88 h1.52
  text "5" at 247.405,179.832 h1.52
  text "Bottom Layer" at 257.816,179.832 h1.52
  text "Copper" at 281.432,179.832 h1.52
  text "1.40mil" at 303.27,179.832 h1.52
  text "6" at 247.405,176.784 h1.52
  text "Bottom Solder" at 257.816,176.784 h1.52
  text "Solder Resist" at 281.432,176.784 h1.52
  text "0.40mil" at 303.27,176.784 h1.52
  text "3.5" at 319.776,176.784 h1.52
  text "7" at 247.405,173.736 h1.52
  text "Bottom Overlay" at 257.816,173.736 h1.52
  text ".Layer_Name" at 13.386,-25.616 h1.52
M13 Component Bodies Top:
  text ".Layer_Name" at 13.386,-25.616 h1.52
M14 Component Bodies Bottom:
  text ".Layer_Name" at 13.386,-25.616 h1.52
M15 Courtyards Top:
  text ".Layer_Name" at 13.386,-25.616 h1.52
M16 Courtyards Bottom:
  text ".Layer_Name" at 13.386,-25.616 h1.52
